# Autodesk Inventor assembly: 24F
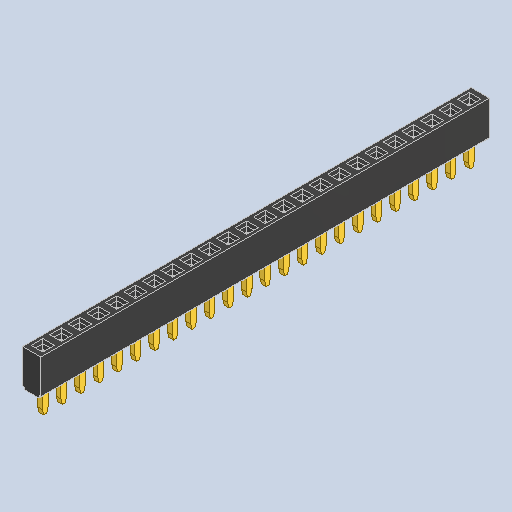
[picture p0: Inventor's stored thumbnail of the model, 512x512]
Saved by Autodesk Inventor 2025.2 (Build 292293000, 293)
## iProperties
Created: 2025-04
Part Number: 24F
Description: PART--DESC
Document SubType Name: Assembly
Designer: BennF
Author: BennF
Revision Number: NONE
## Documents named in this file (3)
- C:\Users\BennF\Nextcloud\Benutzer\CNC JarBeRi\existing parts\Electronics\RepRap A4988 Shied (USE WITHOUT ARDUINO)\reprap-a4988-1.snapshot.1\RepRap\RepRap\24F_1.iam
- C:\Users\BennF\Nextcloud\Benutzer\CNC JarBeRi\existing parts\Electronics\RepRap A4988 Shied (USE WITHOUT ARDUINO)\reprap-a4988-1.snapshot.1\RepRap\RepRap\24F Geometry.ipt
- C:\Users\BennF\Nextcloud\Benutzer\CNC JarBeRi\existing parts\Electronics\RepRap A4988 Shied (USE WITHOUT ARDUINO)\reprap-a4988-1.snapshot.1\RepRap\RepRap\Pin6.ipt
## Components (2 placed, 2 different names)
1. 24F Geometry
2. Pin6
